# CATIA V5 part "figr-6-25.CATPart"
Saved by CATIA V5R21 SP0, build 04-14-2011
Part number: Part1
Bounding box of the stored display mesh (mm): x -70 to 0, y 0 to 90, z -45 to 145
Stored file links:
  D:\CATIA V5R21 E-RESOURCES\CATIA-V5R21\catia-v5r21-prt\c06-catia-v5r21-prt\c06-catia-v5r21-figr-6-25.CATPart
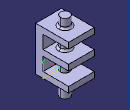
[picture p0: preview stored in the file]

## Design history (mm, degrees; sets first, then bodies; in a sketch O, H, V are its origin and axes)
Body1 (main body)
  Sketch1 on zx-plane, origin (0, 0, 0), H (-1, 0, 0), V (0, 0, 1)
    line L1 (0, 0) -> (70, 0)
    line L2 (70, 0) -> (70, 120)
    line L3 (70, 120) -> (0, 120)
    line L4 (0, 120) -> (0, 0)
    length L3 = 70
    length L2 = 120
    horizontal: L1 H, L3 H
    vertical: L2 V, L4 V
  Pad1: profile Sketch1, direction (0, 1, 0), length 20
  Sketch2 on end face of Pad1, origin (0, 20, 0), H (-1, 0, 0), V (0, 0, 1)
    projected line E1 (70, 120) -> (0, 120) from edge [face of Pad1 from Sketch1.L3 | end face of Pad1]
    point P1 (70, 120)
    line L1 (70, 120) -> (70, 104)
    line L2 (70, 104) -> (0, 104)
    line L3 (0, 104) -> (0, 120)
    point P3 (70, 120)
    length L1 = 16
    horizontal: L2 H
    vertical: L1 V, L3 V
    coincidence: P1 P3
  Sketch3 on end face of Pad1, origin (0, 20, 0), H (-1, 0, 0), V (0, 0, 1)
  Pad2: profile Sketch2, direction (0, 1, 0), length 70
  Sketch4 on end face of Pad1, origin (0, 20, 0), H (-1, 0, 0), V (0, 0, 1)
    projected line E1 (0, 0) -> (70, 0) from edge [face of Pad1 from Sketch1.L1 | end face of Pad1]
    point P1 (0, 0)
    point P3 (0, 16)
    line L1 (0, 16) -> (70, 16)
    line L2 (70, 16) -> (70, 0)
    line L3 (0, 0) -> (0, 16)
    point P5 (0, 0)
    length L2 = 16
    coincidence: P3 V, P1 P5
    horizontal: L1 H
    vertical: L2 V, L3 V
  Pad3: profile Sketch4, direction (0, 1, 0), length 70
  Sketch5 on end face of Pad1, origin (0, 20, 0), H (-1, 0, 0), V (0, 0, 1)
    point P1 (0, 68)
    line L1 (0, 68) -> (70, 68)
    line L2 (70, 68) -> (70, 52)
    line L3 (70, 52) -> (0, 52)
    line L4 (0, 52) -> (0, 68)
    coincidence: P1 V
    horizontal: L1 H, L3 H
    vertical: L2 V, L4 V
  Pad4: profile Sketch5, direction (0, 1, 0), length 70
  Sketch6 on face of Pad2, origin (0, 0, 120), H (1, 0, 0), V (0, 1, 0)
    circle A1 centre (-35, 45) radius 12.5
    radius A1 = 12.5
  Pad5: profile Sketch6, direction (0, 0, 1), length 25, opposite side length 165
  Fillet1: radius 5, on 1 edge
